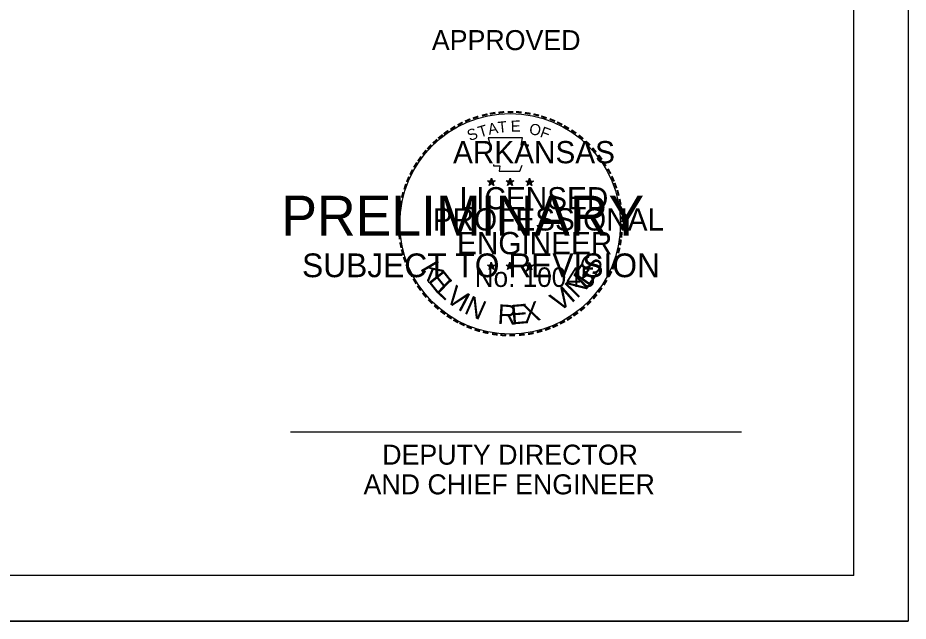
# Model space of a CAD drawing. Extents: x 646058 to 725608, y 1473014 to 1561048.
# Drawn here: x 700985 to 717726, y 1515181 to 1526523 of the extents above; entities that cross this region are included whole.
import ezdxf

# ---------------------------------------------------------------- set-up
doc = ezdxf.new("R2010")
doc.units = 0
for name, color, linetype in [('R_Border Notes', 7, 'Continuous'), ('R_Horz Alg', 7, 'Continuous'), ('R_Temp Easement Annot', 7, 'Continuous'), ('R_Water Annot', 7, 'Continuous'), ('T_Vehicle Path Rt', 7, 'Continuous')]:
    doc.layers.add(name, color=color, linetype=linetype)

msp = doc.modelspace()

# ---------------------------------------------------------------- linework, layer by layer
at = {"layer": 'R_Border Notes'}
for q in [(716704, 1560211), (648725, 1516037)]:
    msp.add_line((716704, 1516037), q, dxfattribs=at)
at = {"layer": 'R_Water Annot'}
for p, q in [((709817, 1523457), (709890, 1523434)), ((709817, 1523457), (709871, 1523449)), ((709817, 1523457), (709866, 1523432)), ((709845, 1523371), (709890, 1523434)), ((709890, 1523511), (709881, 1523457)), ((709890, 1523434), (709890, 1523511)), ((709890, 1523511), (709901, 1523460)), ((709961, 1523457), (709890, 1523434)), ((709935, 1523371), (709890, 1523434)), ((709961, 1523457), (709903, 1523447)), ((709961, 1523457), (709920, 1523436)), ((710167, 1523457), (710240, 1523434)), ((710167, 1523457), (710219, 1523449)), ((710167, 1523457), (710215, 1523432)), ((710193, 1523371), (710240, 1523434)), ((710240, 1523511), (710232, 1523457)), ((710240, 1523434), (710240, 1523511)), ((710240, 1523511), (710249, 1523460)), ((710311, 1523457), (710240, 1523434)), ((710283, 1523371), (710240, 1523434)), ((710311, 1523457), (710251, 1523447)), ((710311, 1523457), (710268, 1523436)), ((710535, 1523455), (710608, 1523432)), ((710535, 1523455), (710587, 1523444)), ((710535, 1523455), (710584, 1523429)), ((710608, 1523507), (710600, 1523455)), ((710608, 1523432), (710608, 1523507)), ((710608, 1523507), (710617, 1523455)), ((710681, 1523455), (710608, 1523432)), ((710681, 1523455), (710619, 1523444)), ((710681, 1523455), (710636, 1523434)), ((709845, 1523371), (709871, 1523423)), ((709845, 1523371), (709888, 1523417)), ((709935, 1523371), (709888, 1523417)), ((709935, 1523371), (709905, 1523432)), ((710193, 1523371), (710221, 1523423)), ((710193, 1523371), (710238, 1523417)), ((710283, 1523371), (710238, 1523417)), ((710283, 1523371), (710253, 1523432)), ((710561, 1523369), (710608, 1523432)), ((710561, 1523369), (710589, 1523421)), ((710561, 1523369), (710608, 1523414)), ((710651, 1523369), (710608, 1523432)), ((710651, 1523369), (710608, 1523414)), ((710651, 1523369), (710623, 1523429)), ((709888, 1521927), (709879, 1521875)), ((709888, 1521851), (709888, 1521927)), ((709888, 1521927), (709899, 1521875)), ((710238, 1521927), (710230, 1521875)), ((710238, 1521851), (710238, 1521927)), ((710238, 1521927), (710247, 1521875)), ((709815, 1521875), (709888, 1521851)), ((709815, 1521875), (709871, 1521864)), ((709815, 1521875), (709866, 1521849)), ((709845, 1521789), (709888, 1521851)), ((709845, 1521789), (709871, 1521841)), ((709845, 1521789), (709888, 1521836)), ((709961, 1521875), (709888, 1521851)), ((709935, 1521789), (709888, 1521851)), ((709935, 1521789), (709888, 1521834)), ((709961, 1521875), (709901, 1521864)), ((709935, 1521789), (709905, 1521849)), ((709961, 1521875), (709920, 1521853)), ((710165, 1521875), (710238, 1521851)), ((710165, 1521875), (710219, 1521864)), ((710165, 1521875), (710215, 1521849)), ((710193, 1521789), (710238, 1521851)), ((710193, 1521789), (710219, 1521841)), ((710193, 1521789), (710238, 1521836)), ((710311, 1521875), (710238, 1521851)), ((710281, 1521789), (710238, 1521851)), ((710281, 1521789), (710238, 1521834)), ((710311, 1521875), (710249, 1521864)), ((710281, 1521789), (710253, 1521849)), ((710311, 1521875), (710266, 1521853)), ((710535, 1521873), (710608, 1521849)), ((710535, 1521873), (710587, 1521862)), ((710535, 1521873), (710584, 1521847)), ((710561, 1521787), (710608, 1521849)), ((710561, 1521787), (710589, 1521838)), ((710561, 1521787), (710608, 1521834)), ((710608, 1521924), (710600, 1521873)), ((710608, 1521849), (710608, 1521924)), ((710608, 1521924), (710617, 1521873)), ((710681, 1521873), (710608, 1521849)), ((710651, 1521787), (710608, 1521849)), ((710651, 1521787), (710608, 1521832)), ((710681, 1521873), (710619, 1521862)), ((710651, 1521787), (710621, 1521847)), ((710681, 1521873), (710636, 1521851)), ((706112, 1518741), (714591, 1518741))]:
    msp.add_line(p, q, dxfattribs=at)
for points in [[(709826, 1524268), (709881, 1524094)], [(710559, 1524077), (710589, 1524135), (710447, 1524130), (710475, 1524268), (709826, 1524268)], [(709929, 1523763), (709929, 1523743), (710045, 1523739), (710034, 1523640), (710425, 1523640), (710468, 1523752)], [(709890, 1523511), (709935, 1523371), (709817, 1523457), (709961, 1523457), (709845, 1523371), (709890, 1523511)], [(710240, 1523511), (710283, 1523371), (710167, 1523457), (710311, 1523457), (710193, 1523371), (710240, 1523511)], [(710608, 1523507), (710651, 1523369), (710535, 1523455), (710681, 1523455), (710561, 1523369), (710608, 1523507)], [(709888, 1521927), (709935, 1521789), (709815, 1521875), (709961, 1521875), (709845, 1521789), (709888, 1521927)], [(710238, 1521927), (710281, 1521789), (710165, 1521875), (710311, 1521875), (710193, 1521789), (710238, 1521927)], [(710608, 1521924), (710651, 1521787), (710535, 1521873), (710681, 1521873), (710561, 1521787), (710608, 1521924)]]:
    msp.add_lwpolyline(points, dxfattribs=at)
for centre, radius in [((710243, 1522651), 2074), ((709888, 1523433), 36), ((709888, 1523433), 30.2), ((709888, 1523433), 24.2), ((709888, 1523433), 20.7), ((709888, 1523433), 15.6), ((709888, 1523433), 10.4), ((709888, 1523433), 6.2), ((710237, 1523433), 36), ((710237, 1523433), 30.2), ((710237, 1523433), 24.2), ((710237, 1523433), 20.7), ((710237, 1523433), 15.6), ((710237, 1523433), 10.4), ((710237, 1523433), 6.2), ((710606, 1523431), 36), ((710606, 1523431), 30.2), ((710606, 1523431), 24.2), ((710606, 1523431), 20.7), ((710606, 1523431), 15.6), ((710606, 1523431), 10.4), ((710606, 1523431), 6.2), ((709887, 1521851), 36), ((709887, 1521851), 30.2), ((709887, 1521851), 24.2), ((709887, 1521851), 20.7), ((709887, 1521851), 15.6), ((709887, 1521851), 10.4), ((709887, 1521851), 6.2), ((710236, 1521851), 36), ((710236, 1521851), 30.2), ((710236, 1521851), 24.2), ((710236, 1521851), 20.7), ((710236, 1521851), 15.6), ((710236, 1521851), 10.4), ((710236, 1521851), 6.2), ((710605, 1521849), 36), ((710605, 1521849), 30.2), ((710605, 1521849), 24.2), ((710605, 1521849), 20.7), ((710605, 1521849), 15.6), ((710605, 1521849), 10.4), ((710605, 1521849), 6.2)]:
    msp.add_circle(centre, radius, dxfattribs=at)
at = {"layer": 'T_Vehicle Path Rt'}
msp.add_line((646059, 1515182), (717726, 1515182), dxfattribs=at)
msp.add_lwpolyline([(646058, 1561048), (717726, 1561048), (717726, 1515181), (646058, 1515181)], close=True, dxfattribs=at)

# ---------------------------------------------------------------- texts
at = {"layer": 'R_Horz Alg'}
for s, height, p in [('PRELIMINARY', 752.5, (705940, 1522427)), ('SUBJECT TO REVISION', 446.15, (706329, 1521647))]:
    msp.add_text(s, height=height, rotation=360, dxfattribs=at).set_placement(p)
at = {"layer": 'R_Temp Easement Annot'}
for s, rotation, p in [('K', 300.3165, (708543, 1521815)), ('S', 62.3127, (711854, 1521653)), ('E', 308.5548, (708681, 1521580)), ('E', 54.9509, (711713, 1521455)), ('L', 315.9166, (708831, 1521388)), ('N', 45.6609, (711500, 1521233)), ('V', 323.2784, (709004, 1521218)), ('V', 32.6901, (711150, 1520987)), ('I', 41.4542, (711393, 1521145)), ('I', 332.0425, (709237, 1521046)), ('N', 336.2493, (709358, 1520976)), ('R', 356.6696, (709998, 1520772)), ('E', 4.9079, (710270, 1520757)), ('X', 12.2697, (710512, 1520776))]:
    msp.add_text(s, height=367, rotation=rotation, dxfattribs=at).set_placement(p)
at = {"layer": 'R_Water Annot'}
for s, height, rotation, p in [('APPROVED', 376.2, 360, (708770, 1525915)), ('-', 334, 0.1862, (710176, 1524625)), ('-', 334, 24.3072, (709430, 1524449)), ('-', 334, 19.1761, (709565, 1524504)), ('-', 334, 13.6301, (709722, 1524554)), ('-', 334, 10.2193, (709862, 1524588)), ('-', 334, 5.8968, (710015, 1524610)), ('-', 334, 357.743, (710326, 1524623)), ('-', 334, 352.1617, (710481, 1524610)), ('-', 334, 347.2049, (710632, 1524588)), ('-', 334, 342.3362, (710767, 1524554)), ('-', 334, 337.8551, (710918, 1524509)), ('-', 334, 34.0636, (709174, 1524304)), ('-', 334, 28.7918, (709299, 1524382)), ('S', 209, 21.594, (709482, 1524201)), ('T', 209, 16.4036, (709673, 1524270)), ('A', 209, 11.2132, (709845, 1524322)), ('T', 209, 6.0228, (710021, 1524358)), ('E', 209, 0.8323, (710253, 1524382)), ('O', 209, 350.4515, (710589, 1524337)), ('F', 209, 340.0707, (710789, 1524289)), ('-', 334, 334.1211, (711051, 1524453)), ('-', 334, 329.6409, (711171, 1524393)), ('-', 334, 38.9507, (708955, 1524143)), ('-', 334, 36.2317, (709052, 1524223)), ('-', 334, 325.8627, (711305, 1524317)), ('-', 334, 320.5297, (711434, 1524229)), ('-', 334, 48.4231, (708770, 1523954)), ('-', 334, 42.9622, (708864, 1524055)), ('ARKANSAS', 418, 360, (709168, 1523788)), ('-', 334, 315.5786, (711558, 1524126)), ('-', 334, 50.6142, (708684, 1523855)), ('-', 334, 309.8797, (711677, 1524010)), ('-', 334, 306.6522, (711788, 1523885)), ('-', 334, 58.0706, (708531, 1523625)), ('-', 334, 54.2325, (708600, 1523735)), ('-', 293, 303.6753, (711887, 1523767)), ('-', 334, 62.8713, (708465, 1523496)), ('-', 334, 299.6684, (711956, 1523638)), ('-', 334, 67.7743, (708411, 1523369)), ('-', 334, 294.6628, (712025, 1523511)), ('-', 334, 72.3945, (708368, 1523238)), ('LICENSED', 418, 360, (709292, 1522922)), ('-', 334, 290.5728, (712077, 1523393)), ('-', 334, 285.1233, (712126, 1523270)), ('-', 334, 75.461, (708325, 1523088)), ('-', 334, 280.5493, (712169, 1523113)), ('-', 334, 85.1863, (708282, 1522795)), ('-', 334, 81.2013, (708299, 1522939)), ('PROFESSIONAL', 417.96, 360, (708787, 1522524)), ('-', 334, 276.5962, (712201, 1522956)), ('-', 334, 89.0622, (708278, 1522649)), ('-', 334, 274.3301, (712214, 1522804)), ('-', 334, 94.1959, (708284, 1522496)), ('-', 334, 269.9407, (712221, 1522670)), ('-', 334, 98.9479, (708299, 1522359)), ('ENGINEER', 418, 360, (709243, 1522079)), ('-', 334, 263.5172, (712216, 1522533)), ('-', 334, 101.7149, (708327, 1522204)), ('-', 334, 260.9953, (712201, 1522395)), ('-', 334, 105.4578, (708361, 1522079)), ('-', 334, 255.7626, (712180, 1522253)), ('-', 334, 109.0874, (708404, 1521948)), ('-', 334, 252.8681, (712141, 1522103)), ('-', 334, 114.0643, (708458, 1521823)), ('-', 334, 115.7289, (708523, 1521694)), ('No. 10045', 367.2, 360, (709576, 1521464)), ('-', 334, 244.6197, (712040, 1521832)), ('-', 334, 247.8887, (712096, 1521963)), ('-', 334, 120.4471, (708598, 1521572)), ('-', 334, 239.0712, (711958, 1521675)), ('-', 334, 125.8934, (708680, 1521456)), ('-', 334, 233.8452, (711874, 1521540)), ('-', 334, 130.7181, (708778, 1521337)), ('-', 334, 231.2538, (711784, 1521419)), ('-', 334, 134.2238, (708886, 1521226)), ('-', 334, 138.9338, (708996, 1521129)), ('-', 334, 221.0851, (711576, 1521196)), ('-', 334, 225.7653, (711683, 1521303)), ('-', 334, 144.6463, (709112, 1521043)), ('-', 334, 148.0898, (709228, 1520966)), ('-', 334, 215.7363, (711460, 1521099)), ('-', 334, 151.5704, (709348, 1520897)), ('-', 334, 154.6002, (709460, 1520847)), ('-', 334, 204.2516, (711103, 1520875)), ('-', 334, 207.3568, (711232, 1520944)), ('-', 334, 212.2491, (711350, 1521017)), ('-', 334, 158.5612, (709589, 1520794)), ('-', 334, 162.7983, (709733, 1520748)), ('-', 334, 167.5555, (709881, 1520716)), ('-', 334, 173.1155, (710043, 1520692)), ('-', 334, 185.8167, (710524, 1520701)), ('-', 334, 191.2858, (710679, 1520727)), ('-', 334, 195.4743, (710832, 1520770)), ('-', 334, 200.7184, (710974, 1520819)), ('-', 334, 176.5183, (710195, 1520680)), ('-', 334, 181.5918, (710352, 1520684)), ('DEPUTY DIRECTOR', 376.16, 360, (707837, 1518123)), ('AND CHIEF ENGINEER', 376.16, 360, (707485, 1517565))]:
    msp.add_text(s, height=height, rotation=rotation, dxfattribs=at).set_placement(p)

doc.saveas('drawing.dxf')
